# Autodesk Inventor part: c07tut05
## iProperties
Shininess: 64.0
Length Units: 11269
Angle Units: 11279
Time Units: 11290
Mass Units: 11283
Length Display Precision: 3
Angle Display Precision: 2
Compacted: True
Part Number: c07tut05
Document SubType Name: Modeling
Created: 2002-12
Designer: deepak
Density: 1 g/cm^3
Density: 0.0
Volumn: 0.0
Area: 0.0
PropertySet Name: Model Information
Control State: 0
Master: False
Checked Out: False
Author: deepak
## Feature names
1. Loft2
